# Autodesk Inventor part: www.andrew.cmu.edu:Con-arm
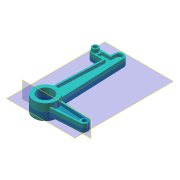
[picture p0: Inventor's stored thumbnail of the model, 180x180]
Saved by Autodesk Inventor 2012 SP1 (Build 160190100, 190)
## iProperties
Shininess: 64.0
Angle Display Precision: 2
Document Length Units: 11272
Document Angle Units: 11279
Document Time Units: 11290
Document Mass Units: 11286
Document Length Units Precision: 3
Document Angle Units Precision: 2
Created: 2008-04
Material: Aluminum-6061
Document SubType Name: Modeling
Density: 2.71 g/cm^3
Mass: 152.334 g
Surface Area: 178.074 cm^2
Volume: 56.2119 cm^3
Density: 7.75
Volumn: 70.48194164286372
Area: 189.76461835308353
PropertySet Name: Model Information
Control State: 0
Master: False
Checked Out: False
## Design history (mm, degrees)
extrude "ExtrusionMidplane1" new body stored distance "d2" = 25.4; taper "d3" = 0 deg
  node "Sketch1" dims "d1" = 38.1
sketch "Sketch2"
  geometry: L1 (12.7, 0)-(7.627, 120.969); L2 (0, 0)-(12.7, 0); L3 (0, 0)-(-12.7, 0); L4 (-12.7, 0)-(-7.6, 120.971); C1 r 19.05 at (0, 0) reference; A1 r 7.62 centre (0.014, 120.65) between (7.627, 120.969) and (-7.6, 120.971)
  constraints: 8 end point, 2 point on circle, 2 tangent, 1 centre point, 1 coincident, 1 collinear, 1 horizontal
  dimensions: "d8" = 12.7 distance of C1.centre L1.start; "d120" = 15.24 diameter of A1; "d121" = 120.65 distance from line of L2 A1.centre; "d140" = 12.7 distance of L2.start L3.end
extrude "ExtrusionMidplane2" join sketch "Sketch2" stored distance "d11" = 12.7; taper "d12" = 0 deg
sketch "Sketch3"
  geometry: L1 (-8.403, 101.921)-(-7.867, 114.621); L2 (-26.65, 101.921)-(-8.403, 101.921); L3 (-12.079, 14.731)-(-7.6, 120.971) reference; L4 (-26.65, 114.621)-(-7.867, 114.621); A1 r 6.35 centre (-26.65, 108.271) between (-26.65, 114.621) and (-26.65, 101.921)
  constraints: 6 end point, 2 point on circle, 2 tangent, 1 centre point, 1 horizontal, 1 parallel, 1 point on line
  dimensions: "d15" = 6.35 radius of A1; "d17" = 180 deg angle of L3 L1; "d19" = 19.05 horizontal distance of L3.end A1.centre; "d21" = 12.7 vertical distance of L3.end A1.centre
extrude "ExtrusionMidplane3" join sketch "Sketch3" stored distance "d22" = 12.7; taper "d23" = 0 deg
sketch "Sketch4"
  geometry: C1 r 5.08 at (-26.65, 108.271); C2 r 5.08 at (-26.65, 108.271); A1 r 6.35 centre (-26.65, 108.271) between (-26.65, 114.621) and (-26.65, 101.921) reference
  constraints: 2 centre point, 2 concentric, 1 coincident
  dimensions: "d79" = 10.16 diameter of C2
extrude "ExtrusionBlind1" join sketch "Sketch4" distance "d25" = 5.588; taper "d26" = 0 deg
sketch "Sketch7"
  geometry: C1 r 5.08 at (0, 0) reference
hole "Hole3" sketch "Sketch7" diameter "d46" = 6.35; stored, may be unused: countersink angle "d50" = 82 deg, drill point angle "d52" = 118 deg; dims "d47" = 12.7, "d48" = 9.525, "d49" = 6.35, "d51" = 19.05
sketch "Sketch14"
  geometry: L1 (0, -11.113)-(63.973, -6.332); L2 (64.072, 6.324)-(0, 11.113); L3 (0, 11.113)-(0, -11.113); A1 r 6.35 centre (63.5, 0) between (63.973, -6.332) and (64.072, 6.324); 2 further points
  constraints: 6 end point, 2 point on circle, 1 centre point, 1 coincident, 1 horizontal alignment, 1 midpoint, 1 tangent, 1 vertical
  dimensions: "d100" = 22.225 distance of L2.end L1.start; "d101" = 6.35 radius of A1; "d102" = 63.5 distance from line of A1.centre L3
extrude "Extrusion9" join sketch "Sketch14" stored distance "d103" = 12.7; taper "d104" = 0 deg
hole "Hole6" diameter "d107" = 6.35; stored, may be unused: countersink angle "d111" = 82 deg, drill point angle "d113" = 118 deg; dims "d105" = 25.4, "d106" = 25.4, "d108" = 19.05, "d109" = 9.525, "d110" = 6.35, "d112" = 25.4
hole "Hole7" diameter "d124" = 25.4; stored, may be unused: countersink angle "d128" = 82 deg, drill point angle "d130" = 118 deg; dims "d122" = 25.4, "d123" = 25.4, "d125" = 19.05, "d126" = 9.525, "d127" = 6.35, "d129" = 25.4
fillet "Fillet5" dims "d136" = 1.524
sketch "Sketch17"
  geometry: L1 (16.278, 9.896)-(64.072, 6.324) reference; L2 (63.973, -6.332)-(16.278, -9.896) reference; L3 (16.052, 6.871)-(17.818, 6.739); L4 (17.617, 7.249)-(59.535, 4.116); L5 (59.536, -4.117)-(17.617, -7.249); L6 (17.464, -7.611)-(16.115, -7.712); C1 r 3.175 at (63.5, 0) reference; A1 r 19.05 centre (0, 0) between (16.278, 9.896) and (16.278, -9.896) reference; A2 r 19.05 centre (0, 0) between (17.617, -7.249) and (17.617, 7.249); A3 r 5.715 centre (63.5, 0) between (59.535, 4.116) and (59.536, -4.117); 1 further point
  constraints: 8 end point, 6 point on circle, 4 parallel, 2 centre point, 1 concentric
  dimensions: "d142" = 2.54 distance between parallel lines of L1 L4; "d143" = 2.54 distance between parallel lines of L2 L5; "d145" = 2.54 radial gap between concentric circles of A3 C1
extrude "Extrusion12" cut sketch "Sketch17" distance "d146" = 5.08; taper "d147" = 0 deg
mirror "Mirror6"
sketch "Sketch18"
  geometry: L1 (-12.079, 14.731)-(-8.47, 100.333) reference; L2 (7.627, 120.969)-(12.082, 14.728) reference; L3 (5.089, 120.863)-(9.464, 16.533); L4 (-9.461, 16.535)-(-5.062, 120.864); A1 r 19.05 centre (0, 0) between (-12.079, 14.731) and (12.082, 14.728) reference; A2 r 7.62 centre (0.014, 120.65) between (7.627, 120.969) and (-7.6, 120.971) reference; A3 r 5.08 centre (0.014, 120.65) between (5.089, 120.863) and (-5.062, 120.864); 1 further point
  constraints: 4 end point, 4 point on circle, 1 centre point, 1 parallel, 1 tangent, 1 other
  dimensions: "d148" = 2.54 radial gap between concentric circles of A2 A3
extrude "Extrusion13" cut sketch "Sketch18" distance "d149" = 5.08; taper "d150" = 0 deg
mirror "Mirror7"
sketch "Sketch19"
  geometry: L1 (-26.65, 114.621)-(-9.328, 114.621) reference; L2 (-9.992, 101.921)-(-26.65, 101.921) reference; L3 (-26.65, 112.566)-(-23.937, 112.566); L4 (-20.05, 112.081)-(-5.432, 112.081); L5 (-5.753, 104.461)-(-20.05, 104.461); L6 (-24.062, 103.899)-(-26.65, 103.899); L7 (-9.461, 16.535)-(-5.062, 120.864) reference; A1 r 5.08 centre (-26.65, 108.271) between (-23.937, 112.566) and (-24.062, 103.899) reference; A2 r 7.62 centre (-26.65, 108.271) between (-20.05, 104.461) and (-20.05, 112.081); 1 further point
  constraints: 8 end point, 4 parallel, 4 point on circle, 2 point on line, 1 centre point
  dimensions: "d151" = 2.54 radial gap between concentric circles of A2 A1; "d152" = 2.54 distance between parallel lines of L1 L4; "d153" = 2.54 distance between parallel lines of L2 L5
extrude "Extrusion14" cut sketch "Sketch19" distance "d154" = 5.08; taper "d155" = 0 deg
mirror "Mirror8"
body "Solid1"
workplane "Work Plane4"
other parameters: "d0" = 38.1 (derived), "d5" = 15.24 (derived), "d7" = 15.24 (derived), "d9" = 127 (derived), "d14" = 7.62 (derived), "d16" = 180 deg (derived), "d18" = 19.05 (derived), "d20" = 12.7 (derived), "d24" = 0, "d34" = 0, "d35" = 9.525 (derived), "d37" = 7.62 (derived), "d53" = 0 (derived), "d54" = 68.1228 (derived), "d56" = 90 deg (derived), "d58" = 31.75 (derived), "d60" = 17.78 (derived), "d62" = 25.4 (derived), "d64" = 3.175 (derived)
